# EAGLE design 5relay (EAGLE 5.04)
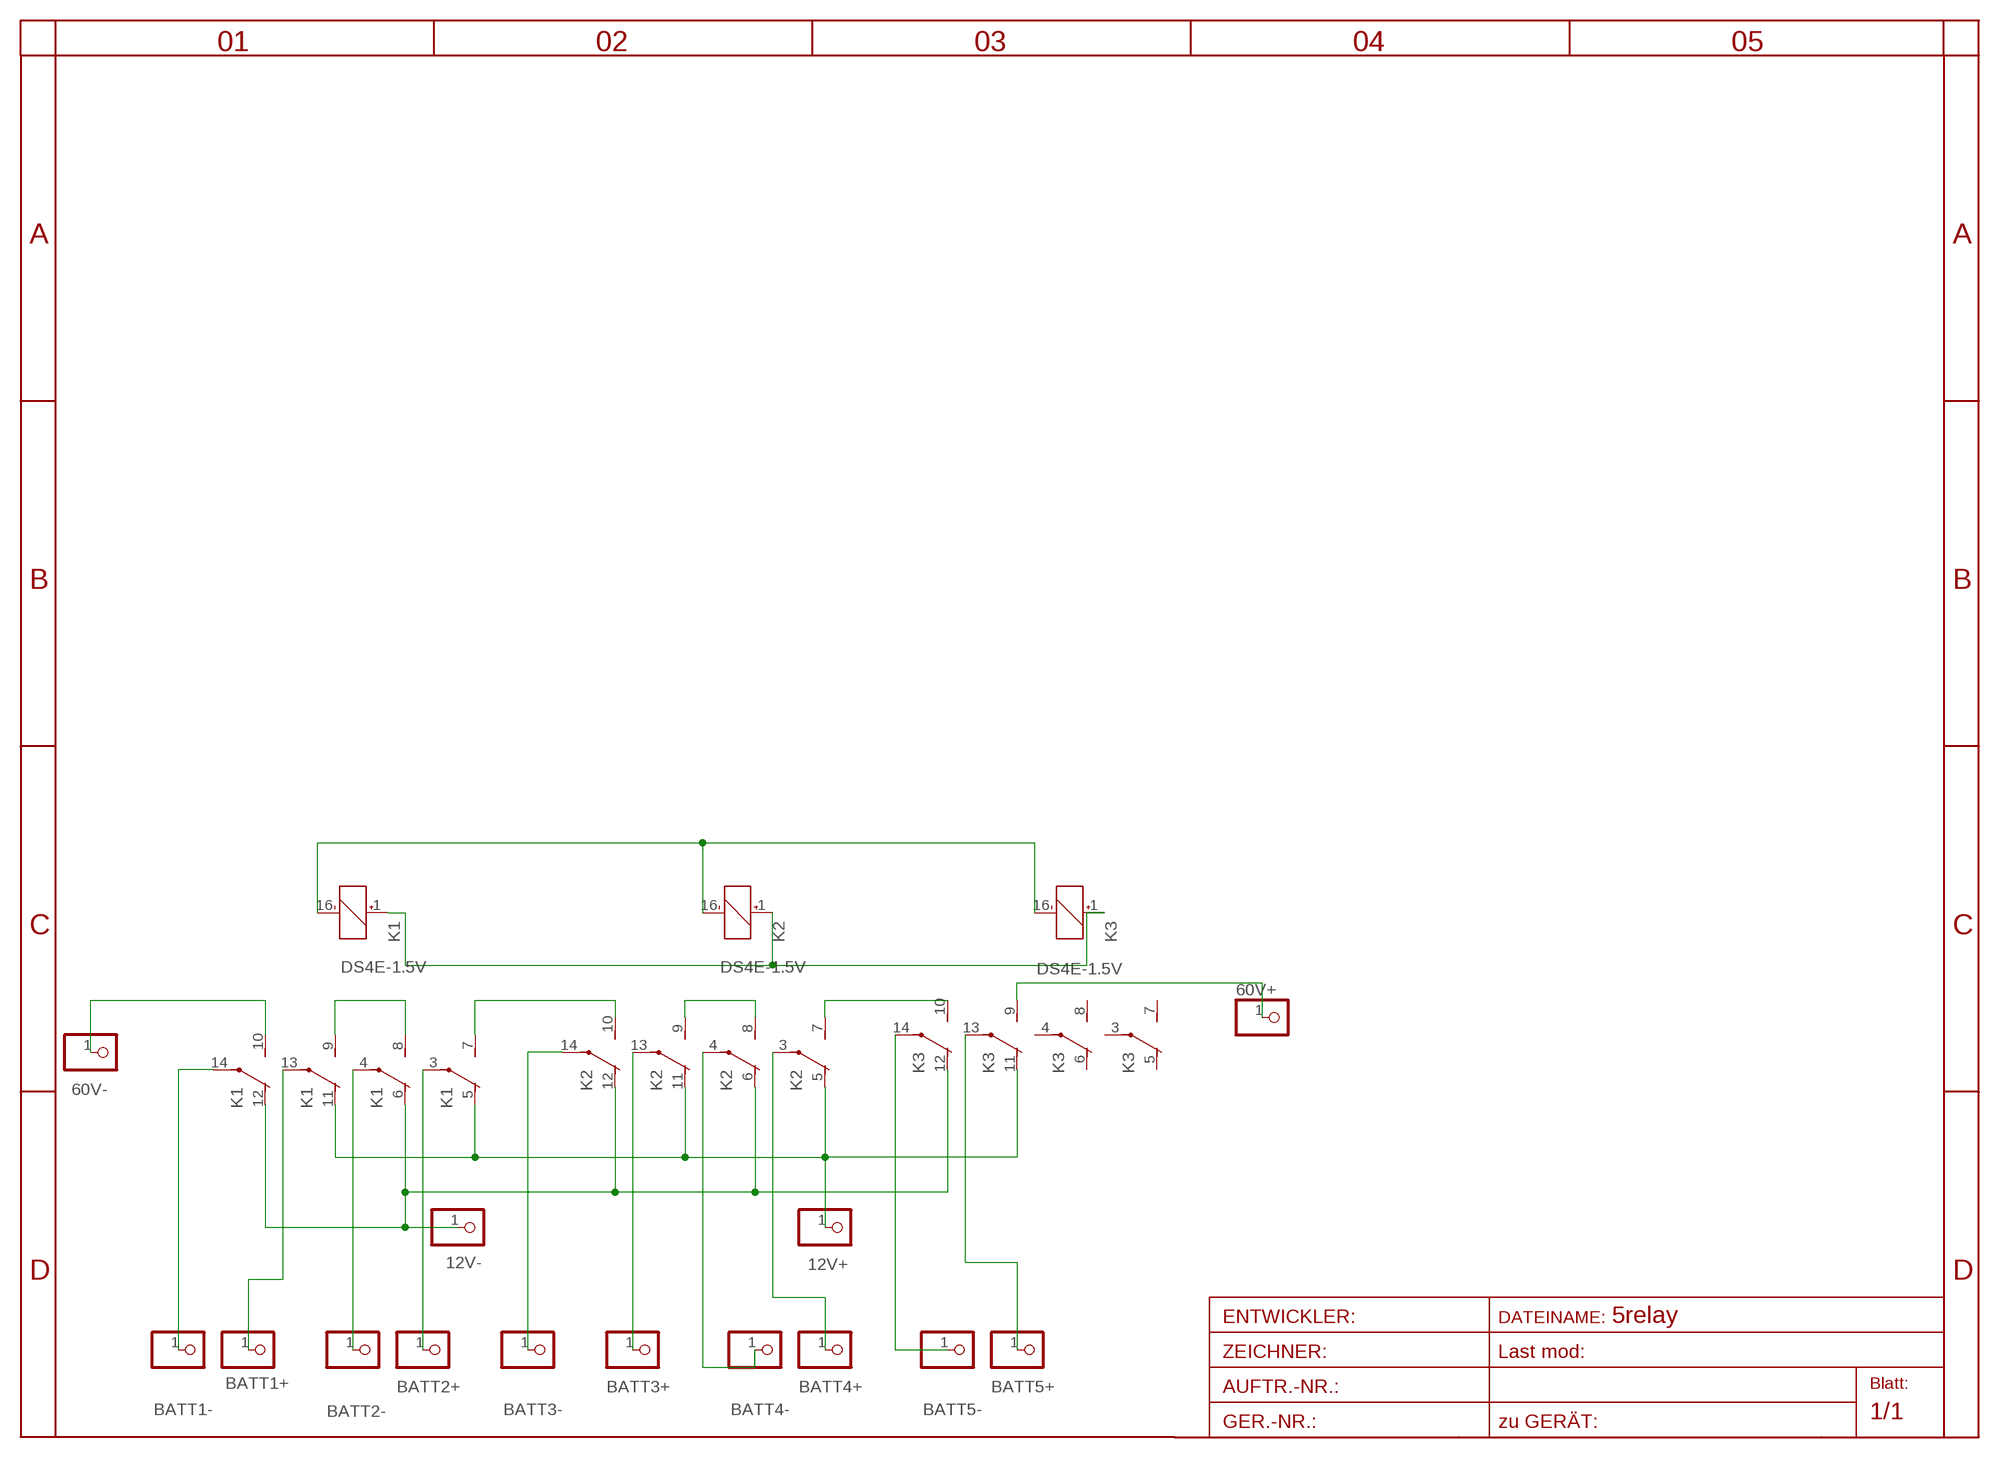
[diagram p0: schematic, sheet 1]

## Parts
12V+  PINHD-1X1  [1X01]
12V-  PINHD-1X1  [1X01]
60V+  PINHD-1X1  [1X01]
60V-  PINHD-1X1  [1X01]
BATT1+  PINHD-1X1  [1X01]
BATT1-  PINHD-1X1  [1X01]
BATT2+  PINHD-1X1  [1X01]
BATT2-  PINHD-1X1  [1X01]
BATT3+  PINHD-1X1  [1X01]
BATT3-  PINHD-1X1  [1X01]
BATT4+  PINHD-1X1  [1X01]
BATT4-  PINHD-1X1  [1X01]
BATT5+  PINHD-1X1  [1X01]
BATT5-  PINHD-1X1  [1X01]
K1  DS4E-1.5V  [DS4E]
K2  DS4E-1.5V  [DS4E]
K3  DS4E-1.5V  [DS4E]

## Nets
BATT1+: BATT1+.1 K1.13(4:P)
BATT1-: BATT1-.1 K1.14(5:P)
N$1: K1.16(1:-) K2.16(1:-) K3.16(1:-)
N$2: K1.1(1:+) K2.1(1:+) K3.1(1:+)
N$3: 60V-.1 K1.10(5:S)
N$4: K1.8(3:S) K1.9(4:S)
N$5: K1.7(2:S) K2.10(5:S)
N$6: 12V-.1 K1.6(3:O) K1.12(5:O) K2.6(3:O) K2.12(5:O) K3.12(5:O)
N$7: 12V+.1 K1.5(2:O) K1.11(4:O) K2.5(2:O) K2.11(4:O) K3.11(4:O)
N$8: BATT3-.1 K2.14(5:P)
N$9: BATT3+.1 K2.13(4:P)
N$10: BATT2-.1 K1.4(3:P)
N$11: BATT2+.1 K1.3(2:P)
N$12: K2.8(3:S) K2.9(4:S)
N$13: K2.7(2:S) K3.10(5:S)
N$14: 60V+.1 K3.9(4:S)
N$17: BATT4-.1 K2.4(3:P)
N$18: BATT4+.1 K2.3(2:P)
N$19: BATT5-.1 K3.14(5:P)
N$20: BATT5+.1 K3.13(4:P)
Unconnected: K3.3(2:P) K3.4(3:P) K3.5(2:O) K3.6(3:O) K3.7(2:S) K3.8(3:S)

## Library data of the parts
12V+ 12V- 60V+ 60V- BATT1+ BATT1- BATT2+ BATT2- BATT3+ BATT3- BATT4+ BATT4- BATT5+ BATT5- = pinhead:PINHD-1X1: PIN HEADER
K1-K3 = relay:DS4E-?*: DS-RELAYS HIGHLY SENSITIVE 1500 V FCC SURGE NAiS WITHSTANDING MINIATURE RELAY Source: http://www.mew-europe.com/.. en_ds_61005_0001.pdf

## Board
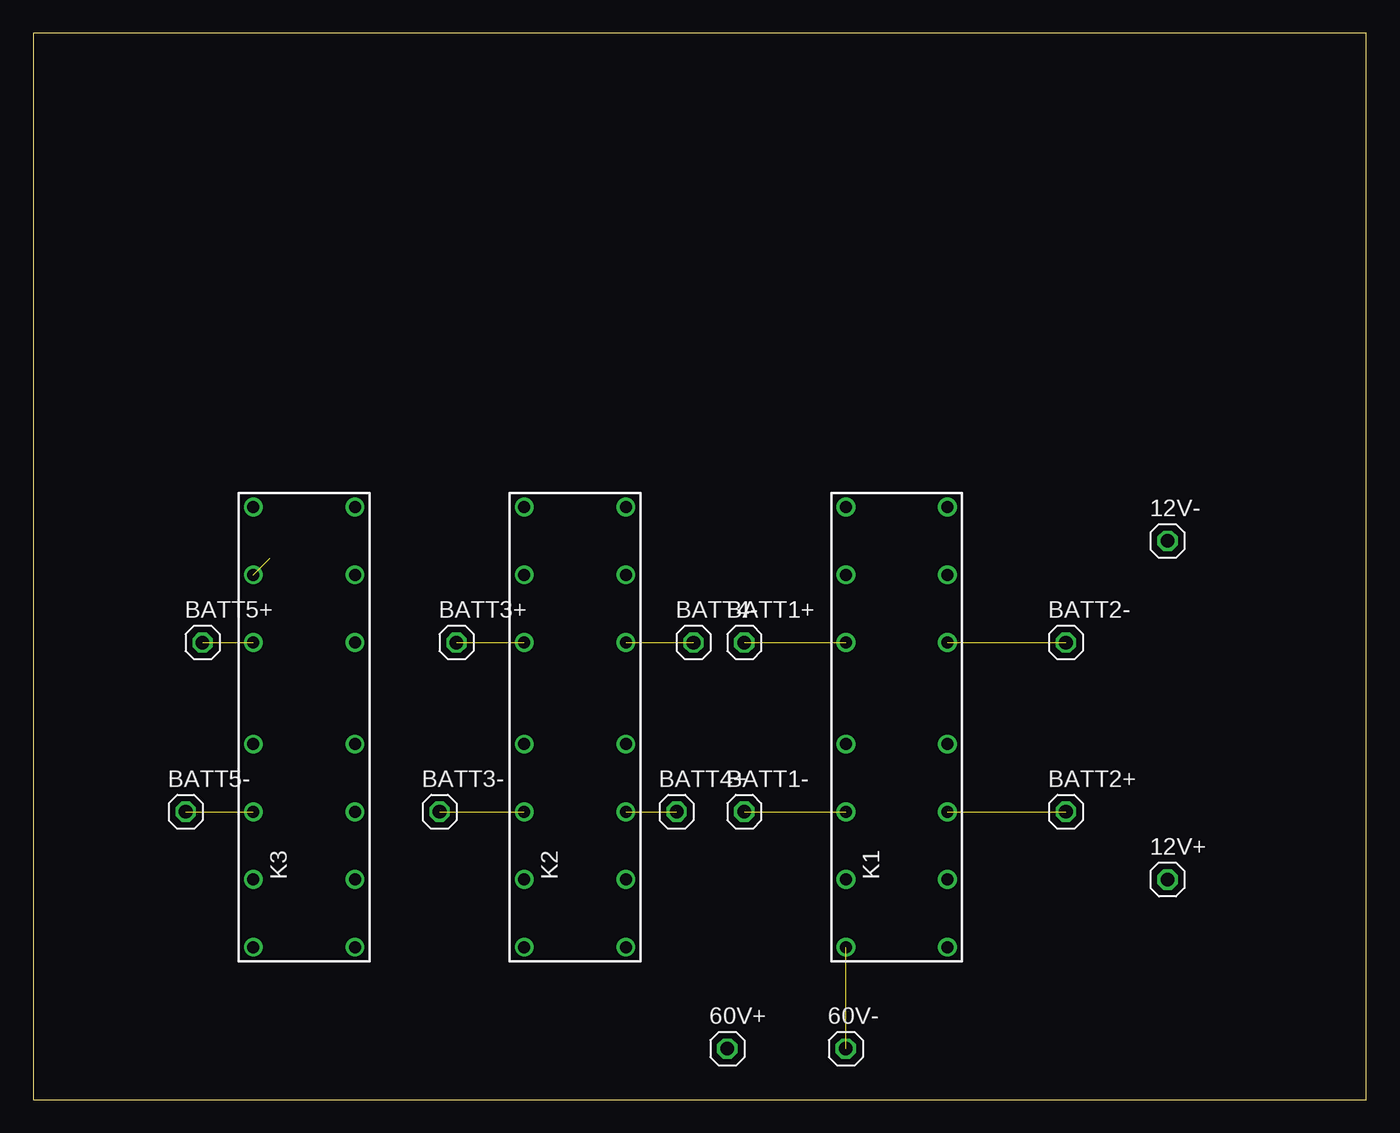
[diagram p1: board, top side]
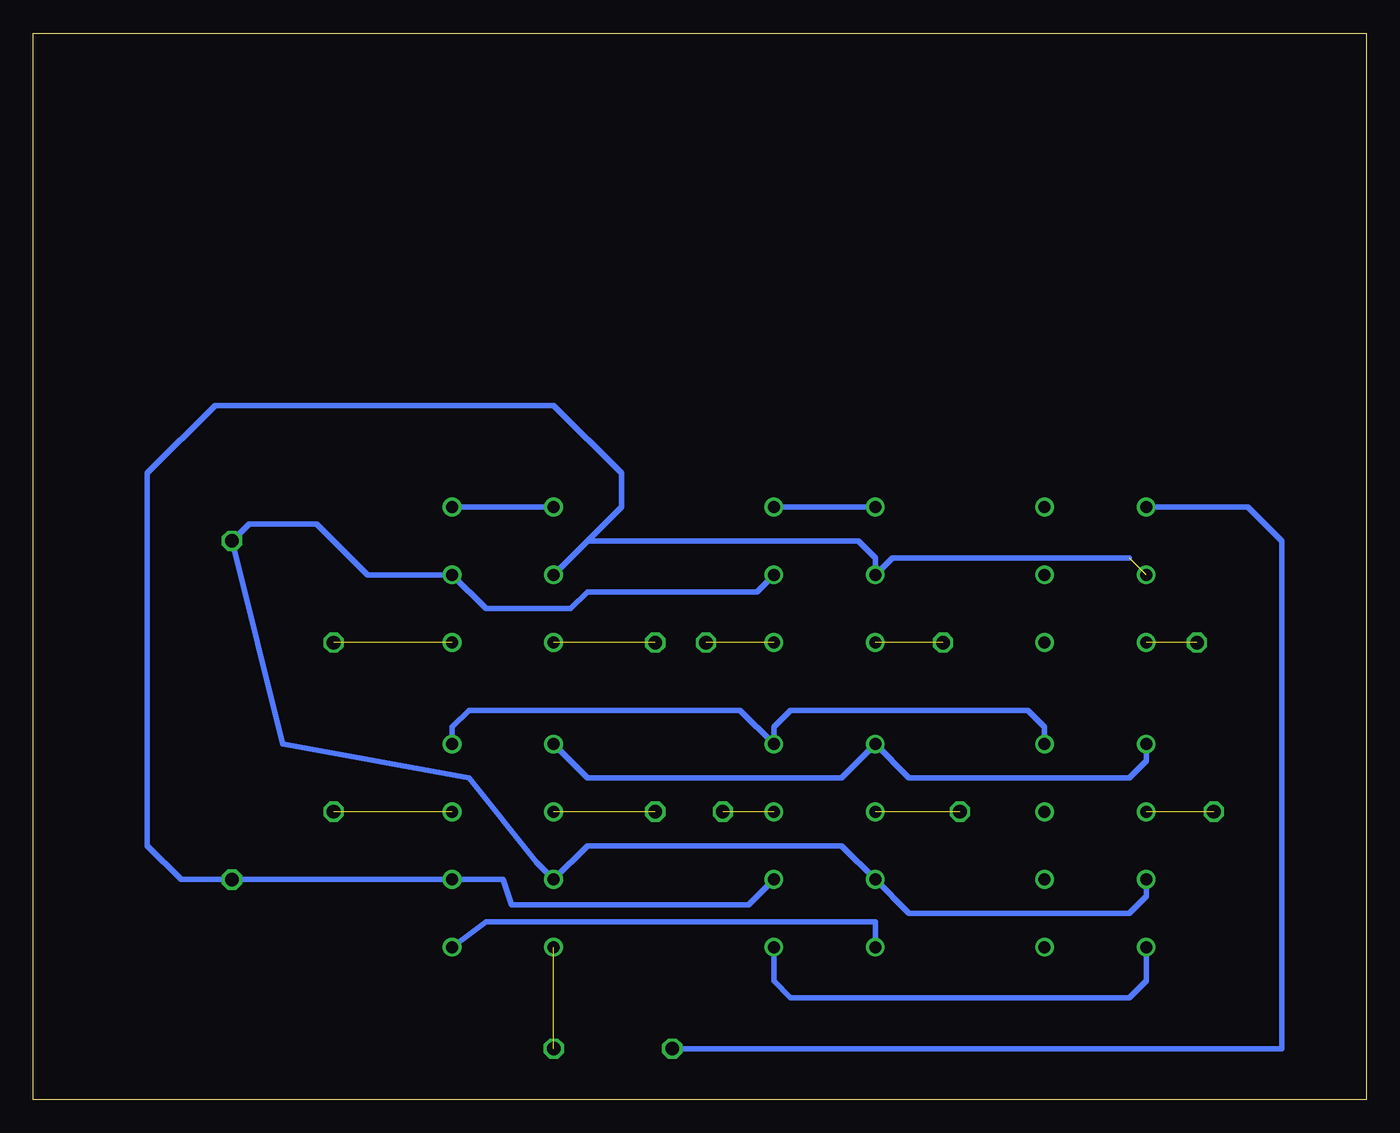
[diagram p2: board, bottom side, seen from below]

Size 100 x 80 mm. Coordinates in mm from the lower left corner, seen from the top.
Outline: 0,0 100,0 100,80 0,80 0,0
Copper layers (1*16): Top 0.035mm / dielectric 1.5mm / Bottom 0.035mm
Design rules "default": minimum track width 10mil, minimum drill 24mil, track to track 8mil, track to pad 8mil, pad to pad 8mil, via to via 8mil, smd to smd 8mil, copper to edge 40mil, drill to drill 8mil, minimum pad ring 10mil, minimum via ring 8mil, stop-mask expansion 4mil, vias tented up to drill 0mil, thermal gap 10mil

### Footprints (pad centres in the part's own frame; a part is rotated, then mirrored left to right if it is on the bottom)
1X01 = drill 1.016 octagon: 1 0,0
DS4E = drill 0.9 round: 1 -1.27,-3.81; 3 -6.35,-3.81; 4 6.35,-3.81; 5 -11.43,-3.81; 6 11.43,-3.81; 7 -16.51,-3.81; 8 16.51,-3.81; 9 16.51,3.81; 10 -16.51,3.81; 11 11.43,3.81; 12 -11.43,3.81; 13 6.35,3.81; 14 -6.35,3.81; 16 -1.27,3.81

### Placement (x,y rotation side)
12V+  85.09,16.51 0 top
12V-  85.09,41.91 0 top
60V+  52.07,3.81 0 top
60V-  60.96,3.81 0 top
BATT1+  53.34,34.29 0 top
BATT1-  53.34,21.59 0 top
BATT2+  77.47,21.59 0 top
BATT2-  77.47,34.29 0 top
BATT3+  31.75,34.29 0 top
BATT3-  30.48,21.59 0 top
BATT4+  48.26,21.59 0 top
BATT4-  49.53,34.29 0 top
BATT5+  12.7,34.29 0 top
BATT5-  11.43,21.59 0 top
K1  64.77,27.94 90 top
K2  40.64,27.94 90 top
K3  20.32,27.94 90 top

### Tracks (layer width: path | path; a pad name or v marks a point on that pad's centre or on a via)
BATT1+  (1 unrouted)
BATT1-  (1 unrouted)
N$1
  Bottom 0.406: K3.16 16.51,25.4 17.78,24.13 34.29,24.13 K2.16 39.37,24.13 58.42,24.13 K1.16
N$2
  Bottom 0.406: K3.1 24.13,27.94 25.4,29.21 43.18,29.21 44.45,27.94 K2.1 46.99,29.21 67.31,29.21 68.58,27.94 K1.1
N$3  (1 unrouted)
N$4
  Bottom 0.406: K1.9 K1.8
N$5
  Bottom 0.406: K2.10 36.83,13.34 66.04,13.34 K1.7
N$6
  Bottom 0.406: K3.12 16.51,15.24 17.78,13.97 34.29,13.97 K2.12 39.37,19.05 58.42,19.05 K1.12 62.23,17.78 67.31,24.13 81.28,26.67 12V-.1 83.82,43.18 78.74,43.18 74.93,39.37 K1.6 66.04,36.83 59.69,36.83 58.42,38.1 45.72,38.1 K2.6
N$7  (1 unrouted)
  Bottom 0.406: 17.78,40.64 35.56,40.64 K2.11 36.83,40.64 38.1,41.91 58.42,41.91 K1.11 55.88,44.45 55.88,46.99 60.96,52.07 86.36,52.07 91.44,46.99 91.44,19.05 88.9,16.51 12V+.1 K1.5 64.77,16.51 64.14,14.61 46.35,14.61 K2.5
N$8  (1 unrouted)
N$9  (1 unrouted)
N$10  (1 unrouted)
N$11  (1 unrouted)
N$12
  Bottom 0.406: K2.9 K2.8
N$13
  Bottom 0.406: K3.10 16.51,8.89 17.78,7.62 43.18,7.62 44.45,8.89 K2.7
N$14
  Bottom 0.406: 60V+.1 6.35,3.81 6.35,41.91 8.89,44.45 K3.9
N$17  (1 unrouted)
N$18  (1 unrouted)
N$19  (1 unrouted)
N$20  (1 unrouted)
